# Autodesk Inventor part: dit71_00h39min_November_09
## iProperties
Company: voestalpine
Created: 2009-11
Part Number: dit71_00h39min_November_09
Material: S235JRG2 (1.0038)
Document SubType Name: Modellieren
Designer: Birklbauer
Mass: 2049.89 g
Surface Area: 231.697 cm^2
Volume: 261.133 cm^3
Density: 7.85 g/cm^3
Stärke: 5
Breite: 0
Höhe: 0
Länge: 0
da: 0
Author: Birklbauer
Keywords: Einzelteile
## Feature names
1. Extrusion1
2. Extrusion2
3. Umdrehung1 [Revolution]
4. Umdrehung2 [Revolution]
5. Umdrehung3 [Revolution]
6. Umdrehung4 [Revolution]
7. Spiegeln1 [Mirror]
8. Rundung2 [Fillet]
9. Spiegeln2 [Mirror]
10. Rundung3 [Fillet]
11. Rundung5 [Fillet]
